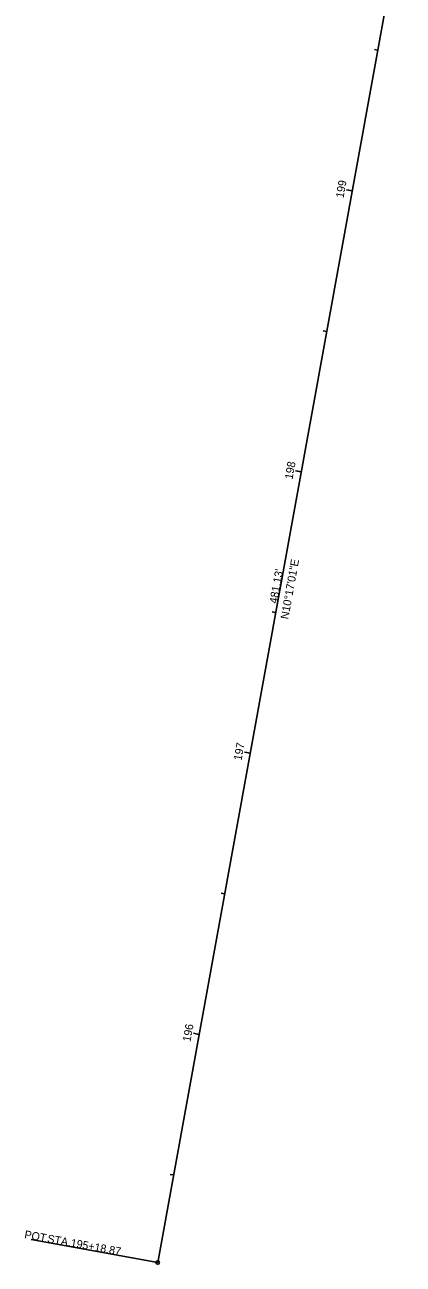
# Model space of a CAD drawing. Extents: x 216512 to 216645, y 458360 to 459225.
# Drawn here: x 216512.1 to 216644.5, y 458359.6 to 458793.3 of the extents above; entities that cross this region are included whole.
import ezdxf

# ---------------------------------------------------------------- set-up
doc = ezdxf.new("R2010")
doc.units = 0
for name, color, linetype in [('RW_X_CL', 7, 'Continuous'), ('RW_X_CL_100_Bearings', 7, 'Continuous'), ('RW_X_CL_100_Cardinal_Points', 7, 'Continuous'), ('RW_X_CL_100_Distances', 7, 'Continuous'), ('RW_X_CL_100_Stations', 7, 'Continuous'), ('RW_X_CL_500_Bearings', 7, 'Continuous'), ('RW_X_CL_500_Cardinal_Points', 7, 'Continuous'), ('RW_X_CL_500_Distances', 7, 'Continuous'), ('RW_X_CL_500_Stations', 7, 'Continuous')]:
    doc.layers.add(name, color=color, linetype=linetype)

msp = doc.modelspace()

# ---------------------------------------------------------------- linework, layer by layer
at = {"layer": 'RW_X_CL'}
msp.add_line((216558.59, 458360.2), (216644.48, 458833.6), dxfattribs=at)
at = {"layer": 'RW_X_CL_100_Cardinal_Points'}
msp.add_line((216558.59, 458360.2), (216514.31, 458368.24), dxfattribs=at)
msp.add_circle((216558.59, 458360.2), 0.6, dxfattribs=at)
at = {"layer": 'RW_X_CL_100_Stations'}
for p, q in [((216635.56, 458784.41), (216634.38, 458784.62)), ((216626.63, 458735.21), (216624.66, 458735.57)), ((216617.7, 458686.01), (216616.52, 458686.23)), ((216608.78, 458636.82), (216606.81, 458637.17)), ((216599.85, 458587.62), (216598.67, 458587.83)), ((216590.93, 458538.42), (216588.96, 458538.78)), ((216582, 458489.23), (216580.82, 458489.44)), ((216573.07, 458440.03), (216571.11, 458440.39)), ((216564.15, 458390.83), (216562.97, 458391.05))]:
    msp.add_line(p, q, dxfattribs=at)
at = {"layer": 'RW_X_CL_500_Cardinal_Points'}
msp.add_line((216558.59, 458360.2), (216514.31, 458368.24), dxfattribs=at)
msp.add_circle((216558.59, 458360.2), 0.6, dxfattribs=at)
at = {"layer": 'RW_X_CL_500_Stations'}
for p, q in [((216626.63, 458735.21), (216625.45, 458735.42)), ((216608.78, 458636.82), (216607.6, 458637.03)), ((216590.93, 458538.42), (216589.75, 458538.64)), ((216573.07, 458440.03), (216571.89, 458440.24))]:
    msp.add_line(p, q, dxfattribs=at)

# ---------------------------------------------------------------- texts
at = {"layer": 'RW_X_CL_100_Bearings'}
msp.add_text('N10°17\'01"E', height=2.8, rotation=79.7164, dxfattribs=at).set_placement((216604.27, 458585.11))
at = {"layer": 'RW_X_CL_100_Cardinal_Points'}
for s, p in [('POT', (216511.78, 458368.73)), (' STA. ', (216518.8, 458367.46)), ('195+18.87', (216527.97, 458365.8))]:
    msp.add_text(s, height=2.8, rotation=349.7164, dxfattribs=at).set_placement(p)
at = {"layer": 'RW_X_CL_100_Distances'}
msp.add_text("481.13'", height=2.8, rotation=79.7164, dxfattribs=at).set_placement((216600.35, 458590.58))
at = {"layer": 'RW_X_CL_100_Stations'}
for s, p in [('199', (216623.59, 458732.48)), ('198', (216605.74, 458634.06)), ('197', (216587.89, 458535.68)), ('196', (216570.03, 458437.27))]:
    msp.add_text(s, height=2.8, rotation=79.7164, dxfattribs=at).set_placement(p)
at = {"layer": 'RW_X_CL_500_Bearings'}
msp.add_text('N10°17\'01"E', height=2.8, rotation=79.7164, dxfattribs=at).set_placement((216604.27, 458585.11))
at = {"layer": 'RW_X_CL_500_Cardinal_Points'}
for s, p in [('POT', (216511.78, 458368.73)), (' STA. ', (216518.8, 458367.46)), ('195+18.87', (216527.97, 458365.8))]:
    msp.add_text(s, height=2.8, rotation=349.7164, dxfattribs=at).set_placement(p)
at = {"layer": 'RW_X_CL_500_Distances'}
msp.add_text("481.13'", height=2.8, rotation=79.7164, dxfattribs=at).set_placement((216600.35, 458590.58))

doc.saveas('drawing.dxf')
